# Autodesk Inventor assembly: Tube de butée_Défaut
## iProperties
Shininess: 64.0
Length Units: 11269
Angle Units: 11279
Time Units: 11290
Mass Units: 11283
Length Display Precision: 3
Angle Display Precision: 2
Compacted: True
Created: 2006-11
Part Number: Tube de butée_Défaut
Document SubType Name: Assembly
Designer: profs_sti
Density: 0.0
Volumn: 0.0
Area: 0.0
PropertySet Name: Model Information
Control State: 0
Master: False
Checked Out: False
Author: profs_sti
